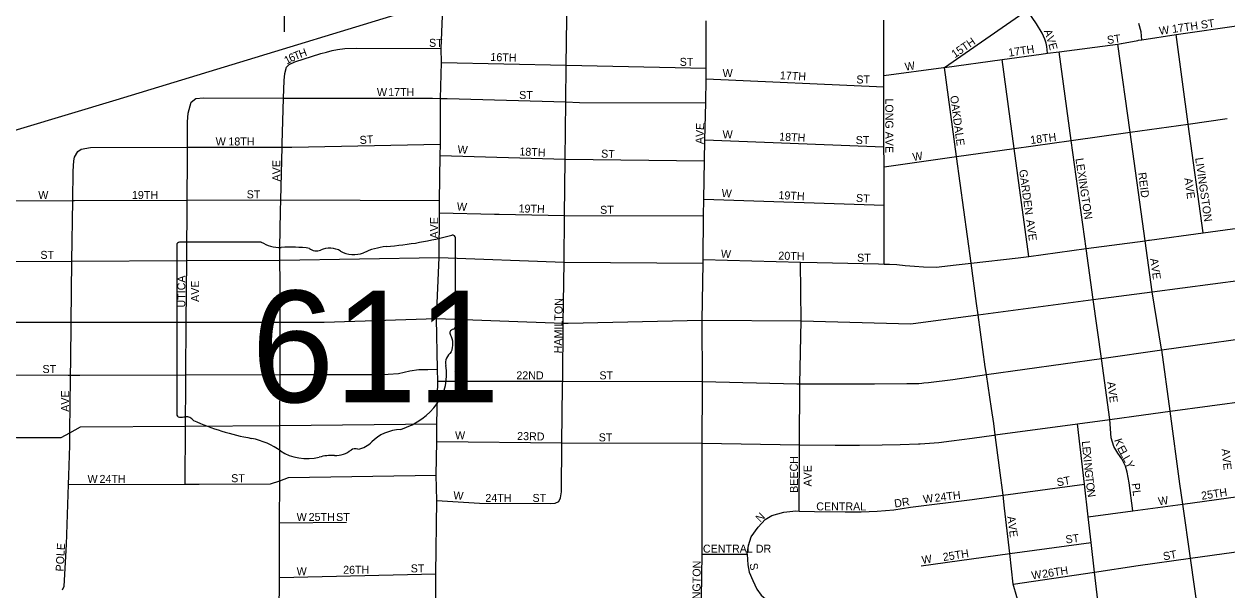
# Model space of a CAD drawing. Extents: x 1857828 to 2277390, y 930619 to 1324581.
# Drawn here: x 2052272 to 2059789, y 1255617 to 1259151 of the extents above; entities that cross this region are included whole.
import ezdxf

# ---------------------------------------------------------------- set-up
doc = ezdxf.new("R2010")
doc.units = 0
for name, color, linetype in [('GM_X_City_Street', 7, 'Continuous'), ('GM_X_City_Street_Text', 7, 'Continuous'), ('GM_X_Rail_Line', 7, 'Continuous'), ('GM_X_State_Location', 7, 'Continuous'), ('GM_X_State_Route', 7, 'Continuous'), ('GM_X_State_Shield', 7, 'Continuous')]:
    doc.layers.add(name, color=color, linetype=linetype)

msp = doc.modelspace()

# ---------------------------------------------------------------- linework, layer by layer
at = {"layer": 'GM_X_City_Street'}
for points in [[(2058668.6, 1258968.7), (2058662.8, 1259010.8), (2058660.5, 1259032.8), (2058650.2, 1259056.9), (2058633.7, 1259094.9), (2058599, 1259152.7), (2058541.7, 1259237.8), (2058321.9, 1259564.8), (2058098.2, 1259897.5), (2057867.7, 1260240.3), (2057780.8, 1260369.7)], [(2058024.2, 1258880.5), (2058541.7, 1259237.8), (2058989.7, 1259547.1), (2059478.5, 1259884.5)], [(2053900.3, 1259102.5), (2053899.4, 1259335.2), (2053899.3, 1259343.5), (2053894.9, 1259684.1)], [(2055637.8, 1256903.3), (2055638, 1256921.8), (2055642.1, 1257283.9), (2055646.5, 1257664.5), (2055649.9, 1257954.5), (2055654, 1258306.7), (2055658.1, 1258664.8), (2055660.8, 1258894), (2055664.1, 1259184.9), (2055666.2, 1259368.8)], [(2054848.2, 1255160.7), (2054844.8, 1255718.4), (2054852.3, 1256174.6), (2054846.6, 1256333.5), (2054852.3, 1256544.1), (2054852.3, 1256653.4), (2054858, 1256920.3), (2054856.1, 1256996), (2054848.5, 1257312.1), (2054865.6, 1257692.5), (2054869.2, 1257972.5), (2054867.5, 1258048.4), (2054873.2, 1258331), (2054875.1, 1258400.4), (2054874.1, 1258687.3), (2054880.7, 1258911.5), (2054878.8, 1258998.5), (2054886.5, 1259203.5)], [(2056510.7, 1257302.8), (2056516.3, 1257657.9), (2056516.5, 1257680.5), (2056518.8, 1257952.5), (2056519.8, 1258056.8), (2056523.3, 1258296), (2056525.6, 1258429), (2056531.6, 1258659.9), (2056535, 1258809), (2056535, 1258876.1), (2056534.8, 1259172.1)], [(2057646.2, 1258282.5), (2057646.2, 1258283.1), (2057646, 1258384.2), (2057645, 1258760.1), (2057644.9, 1258830.3), (2057644.1, 1259165), (2057644.1, 1259175.2)], [(2059231.7, 1259049), (2059235.7, 1259049.7), (2059256.9, 1259053.7), (2059252.9, 1259102), (2059238.9, 1259154.2)], [(2059256.9, 1259053.7), (2059471.1, 1259085.6), (2059878.9, 1259143.9)], [(2059640.6, 1257847.3), (2059547.6, 1258526.9), (2059471.1, 1259085.6)], [(2053911.4, 1258881.5), (2053928.7, 1258897.8), (2053964.6, 1258916.2), (2054126.5, 1258968), (2054162.5, 1258976.4), (2054196.5, 1258986.8), (2054230.5, 1258993.2), (2054276.6, 1258997.6), (2054350.7, 1259000.3), (2054878.8, 1258998.5)], [(2058024.4, 1258880.5), (2058384.6, 1258930), (2058628.4, 1258963.5), (2058668.6, 1258968.7), (2058740.1, 1258978), (2059108.3, 1259025.9)], [(2059321.9, 1257478.7), (2059277.8, 1257798.1), (2059184.2, 1258475.9), (2059108.3, 1259025.9), (2059128, 1259029.6)], [(2059128, 1259029.6), (2059129.5, 1259029.9), (2059231.7, 1259049)], [(2058551.7, 1257699.9), (2058460.1, 1258374.1), (2058384.6, 1258930)], [(2059057.6, 1256681.8), (2059005, 1257062.6), (2058954.1, 1257430.2), (2058910.1, 1257748.4), (2058816.7, 1258424.2), (2058740.1, 1258978)], [(2053871.8, 1257024.1), (2053872.5, 1257289.9), (2053872.6, 1257303), (2053871.6, 1257538), (2053870.9, 1257676.8), (2053870.5, 1257752.9), (2053875.5, 1257981.9), (2053877.1, 1258052.7), (2053884.8, 1258383), (2053885.3, 1258403.6), (2053893.7, 1258688.9), (2053897, 1258799.2), (2053901.2, 1258843.4), (2053911.4, 1258881.5)], [(2054880.7, 1258911.5), (2055660.8, 1258894), (2056535, 1258876.1)], [(2057644.9, 1258830.3), (2058018.8, 1258879.8), (2058024.2, 1258880.5), (2058024.4, 1258880.5)], [(2058539, 1255019.9), (2058496.6, 1255319.4), (2058499.1, 1255494.6), (2058454.1, 1255652.4), (2058432.3, 1255843.4), (2058399.7, 1256128.6), (2058389.9, 1256207.9), (2058368.7, 1256379.9), (2058341.3, 1256585.1), (2058331.7, 1256657.3), (2058318.1, 1256749.8), (2058286.5, 1256961.5), (2058279.1, 1257011.1), (2058234.2, 1257335.2), (2058224.6, 1257405.1), (2058190.3, 1257657.4), (2058099.8, 1258323.5), (2058024.2, 1258880.5)], [(2056535, 1258809), (2057645, 1258760.1)], [(2053282.9, 1256906.5), (2053283, 1256914.3), (2053283.3, 1256960.3), (2053285.7, 1257289.7), (2053288.5, 1257673.9), (2053291.2, 1258051.1), (2053293.1, 1258310.5), (2053293.4, 1258381.7), (2053294.1, 1258541.5), (2053298.3, 1258595.7), (2053316.6, 1258663.9)], [(2053316.6, 1258663.9), (2053344.8, 1258685.8), (2053393, 1258689.6), (2053893.7, 1258688.9), (2054825.4, 1258687.5), (2054874.1, 1258687.3), (2054903.3, 1258687.1), (2054913.7, 1258687), (2054916.7, 1258687)], [(2054916.7, 1258687), (2055658.1, 1258664.8), (2055742.1, 1258662.3), (2056531.6, 1258659.9)], [(2057646.2, 1258259.7), (2058099.8, 1258323.5), (2058460.1, 1258374.1), (2058816.7, 1258424.2), (2059184.2, 1258475.9), (2059547.6, 1258526.9), (2059789.9, 1258561)], [(2052607.1, 1258354.6), (2052629.3, 1258370.5), (2052687.5, 1258380.2), (2053293.4, 1258381.7), (2053884.8, 1258383), (2053945.4, 1258383.2), (2054875.1, 1258400.4)], [(2056525.6, 1258429), (2057646, 1258384.2)], [(2052563.1, 1256961.3), (2052563.4, 1257045.2), (2052566.5, 1257289.3), (2052571.4, 1257670.4), (2052576.2, 1258049.1), (2052578.5, 1258232.2), (2052582.8, 1258296.5), (2052586.9, 1258320.5), (2052607.1, 1258354.6)], [(2054873.2, 1258331), (2055654, 1258306.7), (2056523.3, 1258296)], [(2057647.7, 1257652.3), (2057646.8, 1258020.7), (2057646.2, 1258259.7), (2057646.2, 1258282.5)], [(2051367.9, 1258042.2), (2051457.5, 1258046), (2052576.2, 1258049.1), (2052577.8, 1258049.1), (2052587.4, 1258049.2)], [(2052587.4, 1258049.2), (2053291.2, 1258051.1), (2053877.1, 1258052.7), (2054867.5, 1258048.4)], [(2056519.8, 1258056.8), (2057646.8, 1258020.7)], [(2054869.2, 1257972.5), (2055211.5, 1257964.6), (2055241.6, 1257963.9)], [(2055241.6, 1257963.9), (2055649.9, 1257954.5), (2056518.8, 1257952.5)], [(2059305.2, 1257801.8), (2059640.6, 1257847.3), (2060038.3, 1257901.1)], [(2056516.5, 1257680.5), (2057123.7, 1257663.5), (2057228.5, 1257661.7), (2057611.7, 1257653.6), (2057647.7, 1257652.3), (2057679.9, 1257651.2), (2057726, 1257648.9), (2057778.2, 1257642.6), (2057836.3, 1257638.2), (2057892.5, 1257633.9), (2057972.8, 1257633.4), (2058097.2, 1257646.8), (2058190.3, 1257657.4), (2058484.6, 1257690.8), (2058551.7, 1257699.9), (2058910.1, 1257748.4), (2059277.8, 1257798.1), (2059298.4, 1257800.9), (2059305.2, 1257801.8)], [(2051371.8, 1257664.5), (2052571.4, 1257670.4), (2053288.5, 1257673.9), (2053870.9, 1257676.8), (2054865.6, 1257692.5), (2055646.5, 1257664.5), (2056516.3, 1257657.9)], [(2057116.5, 1256109.2), (2057118.4, 1256522.4), (2057120.2, 1256903.3), (2057129, 1257297), (2057123.7, 1257663.5)], [(2059757.7, 1253849.1), (2059767.8, 1253889.4), (2059778.7, 1253933.4), (2059751.9, 1254138.8), (2059712.6, 1254439.9), (2059709.1, 1254494.4), (2059708.9, 1254498.2), (2059709.1, 1254550.5), (2059707.4, 1254632.8), (2059705.8, 1254705.1), (2059692.1, 1254799.6), (2059687.4, 1254837.8), (2059649.5, 1255145), (2059608.7, 1255475.2), (2059561, 1255814.5), (2059513.4, 1256153.2), (2059495.7, 1256279.1), (2059434, 1256732.5), (2059381.7, 1257115.6), (2059381, 1257121.4), (2059321.9, 1257478.7)], [(2056512.2, 1256884.5), (2056512.5, 1256918), (2056510.7, 1257302.8)], [(2057895.9, 1256910), (2057923.5, 1256912.6), (2058076.1, 1256931.9), (2058286.5, 1256961.5), (2059005, 1257062.6), (2059381.7, 1257115.6), (2060126.8, 1257220.5)], [(2052553.7, 1256958.8), (2052563.1, 1256958.8), (2052621.2, 1256958.5), (2053283.3, 1256960.3), (2053871.6, 1256961.8), (2054322.5, 1256963), (2054495.1, 1256962), (2054547.2, 1256963.8), (2054611.5, 1256969.4), (2054683.8, 1256985.1), (2054740, 1256992.8), (2054796.2, 1256994.5), (2054856.1, 1256996)], [(2053870, 1256399.6), (2053870.7, 1256644), (2053871.5, 1256952.6), (2053871.6, 1256961.8), (2053871.8, 1257024.1)], [(2051374.4, 1256963.8), (2052546.6, 1256958.9), (2052553.7, 1256958.8)], [(2052557.5, 1256598.5), (2052557.5, 1256599), (2052557.5, 1256599.9), (2052557.5, 1256605.4), (2052563, 1256938.8), (2052563.1, 1256958.8), (2052563.1, 1256961.3)], [(2053278.4, 1256277.3), (2053281, 1256639.8), (2053282.9, 1256906.5)], [(2054858, 1256920.3), (2055638, 1256921.8), (2056512.5, 1256918), (2057100.9, 1256903.2), (2057120.2, 1256903.3), (2057586.4, 1256904.5), (2057789.1, 1256905.4), (2057863.3, 1256907), (2057883.4, 1256908.8), (2057895.9, 1256910)], [(2055613.2, 1256168.4), (2055624.4, 1256191.3), (2055630, 1256229.5), (2055633.6, 1256536.6), (2055637.6, 1256890.4), (2055637.8, 1256903.3)], [(2056500, 1255159), (2056510.7, 1255840.2), (2056509, 1256533.2), (2056512.2, 1256884.5)], [(2058335.6, 1256584.3), (2058341.3, 1256585.1), (2058854.5, 1256654.3), (2059057.6, 1256681.8), (2059268.8, 1256710.2), (2059434, 1256732.5), (2060177.7, 1256832.6)], [(2059201.6, 1256110.7), (2059179.1, 1256285.2), (2059165, 1256351.5), (2059155, 1256389.6), (2059132.9, 1256435.8), (2059106.8, 1256472), (2059082.7, 1256512.1), (2059066.6, 1256566.4), (2059057.6, 1256681.8)], [(2051353.5, 1256571.4), (2052224.3, 1256569.1), (2052503.2, 1256569.5), (2052557.5, 1256599), (2052623.8, 1256635.1), (2053281, 1256639.8), (2053870.7, 1256644), (2054852.3, 1256653.4)], [(2052511.2, 1255617.4), (2052523.3, 1255641.4), (2052536.5, 1255900.4), (2052550.3, 1256276.1), (2052552.4, 1256332.2), (2052557.1, 1256519), (2052557.5, 1256598.5)], [(2059205.7, 1253826.9), (2059172.5, 1254060.4), (2059122.4, 1254412.4), (2059113.9, 1254472.4), (2059094.2, 1254612.8), (2059077.2, 1254746.1), (2059072.2, 1254785.3), (2059040.1, 1255060.6), (2059001.8, 1255390.2), (2058962.4, 1255728.3), (2058940.9, 1255912.9), (2058922.3, 1256072.7), (2058898.4, 1256277.4), (2058854.5, 1256654.3)], [(2054852.3, 1256544.1), (2055633.6, 1256536.6), (2056509, 1256533.2), (2057118.4, 1256522.4), (2057340, 1256520.2), (2057492.5, 1256521.4), (2057635, 1256522.6), (2057747.4, 1256526), (2057861.4, 1256529), (2057870.6, 1256529.2)], [(2057870.6, 1256529.2), (2057871.7, 1256529.3), (2057929.9, 1256533), (2057988.1, 1256538.7), (2058068.4, 1256548.2), (2058196.9, 1256565.6), (2058331.7, 1256583.8), (2058335.6, 1256584.3)], [(2053860, 1255114.9), (2053865.1, 1255378.9), (2053866.8, 1255463.1), (2053867.7, 1255693.9), (2053868.4, 1255838.7), (2053868.9, 1256035.4), (2053869.7, 1256299.2), (2053869.7, 1256325), (2053870, 1256399.6)], [(2052550.3, 1256276.1), (2053278.4, 1256277.3), (2053366.7, 1256277.4), (2053812, 1256278.9), (2053869.7, 1256299.2), (2053924.6, 1256318.5), (2054846.6, 1256333.5)], [(2057812.2, 1256133.6), (2058197, 1256181.5), (2058389.9, 1256207.9), (2058898.4, 1256277.4)], [(2058922.3, 1256072.7), (2059201.6, 1256110.7), (2059513.4, 1256153.2), (2059860.3, 1256200.4), (2060253.8, 1256254)], [(2054852.3, 1256174.6), (2055117.6, 1256159.1), (2055561, 1256156.6), (2055591.1, 1256158.4), (2055613.2, 1256168.4)], [(2056790.2, 1255841.2), (2056800.2, 1255895.4), (2056816.2, 1255947.6), (2056860.2, 1256009.8), (2056904.3, 1256055.9), (2056944.3, 1256082), (2057020.5, 1256102), (2057094.6, 1256110), (2057116.5, 1256109.2), (2057210.9, 1256105.9), (2057403.3, 1256103.7), (2057503.6, 1256105.7), (2057603.8, 1256109.6), (2057708, 1256117.6), (2057812.2, 1256133.6)], [(2053868.9, 1256035.4), (2054286.4, 1256039.5)], [(2057877.6, 1255767.6), (2058432.3, 1255843.4), (2058940.9, 1255912.9)], [(2058454.1, 1255652.4), (2058962.4, 1255728.3), (2059235.4, 1255769), (2059561, 1255814.5), (2060298, 1255917.3)], [(2056510.7, 1255840.2), (2056790.2, 1255841.2)], [(2056790.2, 1255841.2), (2056794.2, 1255772.9), (2056804.3, 1255728.7), (2056826.4, 1255676.5), (2056850.5, 1255622.3), (2056878.6, 1255584.1), (2056920.7, 1255547.9), (2056970.8, 1255523.8), (2057047, 1255509.7), (2057105.8, 1255503.8), (2057127.2, 1255501.6), (2057263.5, 1255501.5), (2057377.7, 1255503.5), (2057477.9, 1255505.4), (2057542.1, 1255507.4), (2057584.2, 1255501.3), (2057644.3, 1255491.2), (2057701.2, 1255489.6), (2057820.2, 1255421), (2057867.5, 1255377.4)], [(2053867.7, 1255693.9), (2054844.8, 1255718.4)]]:
    msp.add_lwpolyline(points, dxfattribs=at)
at = {"layer": 'GM_X_Rail_Line'}
msp.add_lwpolyline([(2044683.2, 1256198.2), (2047003.1, 1256900.8), (2049235, 1257574.5), (2049628.9, 1257694.6), (2049728.7, 1257726.8), (2049921.1, 1257796), (2050159.4, 1257869.2), (2051356.3, 1258230.8), (2052847.1, 1258678.3), (2055337.6, 1259437.3), (2056506.8, 1259789.8), (2056581.8, 1259814.4), (2056641.8, 1259834.5), (2056714.6, 1259862.5), (2056780.4, 1259889.1), (2056853.9, 1259922.2), (2056942.1, 1259963.8), (2057085.6, 1260039.1), (2057160.2, 1260084.6), (2057233.4, 1260130.8), (2057527, 1260327), (2057787.1, 1260503.3), (2058204.4, 1260784)], dxfattribs=at)
at = {"layer": 'GM_X_State_Route'}
for points in [[(2054848.5, 1257312.1), (2054848.5, 1257312.1), (2055642.1, 1257283.9), (2055672.5, 1257283.8), (2056510.7, 1257302.8), (2057129, 1257297), (2057814.2, 1257279.8), (2058234.2, 1257335.2), (2058954.1, 1257430.2), (2059321.9, 1257478.7), (2060079.7, 1257578.7)], [(2050157.6, 1257272.9), (2050397.9, 1257275.1), (2051068.4, 1257281.4), (2051376, 1257284.4), (2051874.2, 1257289.1), (2052566.5, 1257289.3), (2053285.7, 1257289.7), (2053872.5, 1257289.9), (2053894.2, 1257289.9), (2053900.1, 1257289.9)], [(2053900.1, 1257289.9), (2054146.7, 1257290.1), (2054848.5, 1257312.1)]]:
    msp.add_lwpolyline(points, dxfattribs=at)
at = {"layer": 'GM_X_State_Shield'}
for p, q in [((2054967.4, 1257263.1), (2054967.4, 1257815.8)), ((2053227.2, 1257771.5), (2053227.2, 1256714.8)), ((2053754, 1257789.7), (2053244.3, 1257789.7)), ((2054967.2, 1257263.2), (2054967.4, 1257263.1))]:
    msp.add_line(p, q, dxfattribs=at)
for centre, major_axis, start_param, end_param in [((2054347.5, 1259230.2), (1845.5, 0), 4.814394, 5.042369), ((2054948.1, 1257818.1), (19.4, 0), 6.141152, 7.989035), ((2053247.1, 1257773.7), (20.2, 0), 1.712693, 3.28349), ((2053875.3, 1257912.3), (195.5, 0), 4.042523, 4.731795), ((2053940.2, 1257196.5), (702, 0), 1.404758, 1.657858), ((2054099.5, 1257779.2), (56.4, 0), 3.836095, 5.185415), ((2054182.3, 1257657.1), (117.3, 0), 0.950623, 2.079405), ((2054333.7, 1257824.6), (141.1, 0), 4.081561, 5.145723), ((2054582.9, 1257466.9), (371.3, 0), 1.699011, 2.107814), ((2054962.9, 1257222.5), (30, 0), 1.883978, 3.671073), ((2054772.2, 1257152.7), (180, 0), 5.934695, 6.695948), ((2054946.7, 1257261), (20.7, 0), 5.05454, 6.418171), ((2055036.8, 1257031.8), (130.9, 0), 2.387724, 3.262537), ((2054450.9, 1256961.5), (461.6, 0), 5.101752, 6.440018), ((2053247.3, 1256712.5), (20.3, 0), 3.00124, 4.508301), ((2053250.4, 1256820.6), (155.2, 0), 4.665946, 4.897461), ((2053282.2, 1256653.9), (56, 0), 0.519207, 1.627899), ((2053988.8, 1257603.2), (1332.7, 0), 4.195997, 4.488961), ((2054645.5, 1256418.2), (252.8, 0), 1.647645, 2.488434), ((2053591.4, 1256240.1), (417, 0), 0.823519, 1.323587), ((2054325.2, 1256612.4), (149.1, 0), 4.937069, 5.64225), ((2054042.4, 1256648.6), (264.6, 0), 4.026481, 4.996735), ((2054195.3, 1256283.3), (217.4, 0), 1.495662, 1.94098), ((2054214.6, 1256569.5), (141, 0), 4.691044, 5.507374), ((2054342.2, 1256467.2), (39.7, 0), 1.147584, 2.315152)]:
    msp.add_ellipse(centre, major_axis=major_axis, ratio=0.8, start_param=start_param, end_param=end_param, dxfattribs=at)

# ---------------------------------------------------------------- texts
at = {"layer": 'GM_X_City_Street_Text'}
for s, rotation, p in [('W 17TH ST', 8.24245, (2059368.9, 1259083.6)), ('A', 290.43323, (2058643.9, 1259108.4)), ('V', 288.46261, (2058659.1, 1259067.6)), ('ST', 7.59083, (2059043.1, 1259026.4)), ('ST', 0.00001, (2054802.7, 1259008.9)), ('15TH', 34.70215, (2058088.6, 1258936.8)), ('17TH', 8.88878, (2058426.9, 1258947.1)), ('E', 284.67262, (2058672.8, 1259026.7)), ('1', 28.3663, (2053913.8, 1258897.7)), ('6', 25.92256, (2053940.4, 1258912.1)), ('T', 21.53763, (2053967.2, 1258925.1)), ('H', 20.26696, (2053999.6, 1258938)), ('16TH', 358.21116, (2055185.8, 1258920.9)), ('ST', 0.00001, (2056369.1, 1258890.1)), ('W', 0.00001, (2056637.5, 1258819.7)), ('17TH', 357.27517, (2056994.4, 1258806.4)), ('W', 8.74111, (2057780.1, 1258859.2)), ('ST', 0.00001, (2057473.5, 1258780.1)), ('W', 0.00001, (2054477.1, 1258700.9)), ('17TH', 0.00001, (2054547.5, 1258700.9)), ('ST', 0.00001, (2055365.9, 1258683.3)), ('OAKDALE', 277.64956, (2058059.3, 1258701.5)), ('LONG AVE', 270, (2057654.5, 1258687)), ('V', 87.79235, (2056519, 1258444.5)), ('E', 87.59586, (2056520.6, 1258488.5)), ('W', 0.00001, (2056637.5, 1258436.9)), ('W', 0.00001, (2053469.5, 1258392.9)), ('18TH', 0.00001, (2053548.7, 1258392.9)), ('ST', 3.57378, (2054370.9, 1258401.7)), ('A', 88.90669, (2056518.1, 1258400.8)), ('18TH', 357.27517, (2056990, 1258423.7)), ('ST', 0.00001, (2057469.1, 1258401.7)), ('18TH', 7.3488, (2058563.5, 1258401.6)), ('W', 355.60387, (2054979.4, 1258344.5)), ('18TH', 357.27517, (2055366.4, 1258331.2)), ('ST', 356.42537, (2055876.9, 1258318.1)), ('W', 8.74363, (2057828.5, 1258296)), ('AVE', 90, (2053873.7, 1258167.9)), ('LEXINGTON', 278.63844, (2058842.4, 1258310.1)), ('LIVINGSTON', 278.22742, (2059590.4, 1258314.4)), ('GARDEN', 277.85294, (2058490.4, 1258239.5)), ('REID', 277.35574, (2059234, 1258221.9)), ('AVE', 278.13339, (2059522.9, 1258187.8)), ('W', 0.00001, (2052360.7, 1258058.5)), ('19TH', 0.00001, (2052945.9, 1258058.5)), ('ST', 0.00001, (2053663.1, 1258062.9)), ('W', 355.60387, (2056629.4, 1258071.6)), ('19TH', 357.27517, (2056985.6, 1258058.5)), ('W', 355.60387, (2054975, 1257988)), ('19TH', 358.63682, (2055361.8, 1257974.9)), ('ST', 356.42537, (2057469.7, 1258040.9)), ('ST', 0.00001, (2055871.9, 1257966.1)), ('AVE', 90, (2054859.3, 1257811.5)), ('AVE', 277.85664, (2058534.4, 1257927.1)), ('ST', 0.00001, (2052373.9, 1257684.5)), ('W', 355.60387, (2056625, 1257693.2)), ('20TH', 358.63682, (2056985.4, 1257680.1)), ('ST', 0.00001, (2057477.9, 1257666.9)), ('AVE', 278.12574, (2059308.9, 1257685.2)), ('UTICA', 90, (2053279.7, 1257380.3)), ('AVE', 90, (2053365.8, 1257415.5)), ('HAMILTON', 89.22505, (2055633.7, 1257094.1)), ('ST', 0.00001, (2052387.1, 1256971.7)), ('W', 0.00001, (2054961.1, 1256932.1)), ('22ND', 0.00001, (2055348.3, 1256932.1)), ('ST', 0.00001, (2055867.5, 1256932.1)), ('AVE', 277.84924, (2059040.4, 1256915.1)), ('AVE', 90, (2052553.7, 1256729.1)), ('W', 0.00001, (2054965.5, 1256558.1)), ('23RD', 358.66861, (2055352.9, 1256553.7)), ('ST', 0.00001, (2055863.1, 1256544.9)), ('L', 275.63452, (2058882.1, 1256545.2)), ('K', 287.35664, (2059084, 1256553.9)), ('E', 298.50239, (2059101.2, 1256502.3)), ('BEECH', 90, (2057107.7, 1256223.1)), ('E', 275.63452, (2058885.6, 1256510.1)), ('X', 275.62793, (2058889, 1256475.1)), ('L', 298.68297, (2059118, 1256471.2)), ('L', 298.66716, (2059134.9, 1256440.3)), ('AVE', 275.90306, (2059755.7, 1256496.8)), ('AVE', 90, (2057193.7, 1256262.7)), ('I', 275.60618, (2058893.3, 1256431.3)), ('N', 275.65184, (2058895.5, 1256409.4)), ('Y', 292.67033, (2059151.2, 1256410.7)), ('W', 0.00001, (2052668.7, 1256285.3)), ('24TH', 0.00001, (2052743.5, 1256285.3)), ('ST', 0.00001, (2053566.3, 1256289.7)), ('ST', 10.61471, (2058730.2, 1256263.1)), ('G', 275.62793, (2058899.8, 1256365.6)), ('T', 275.92091, (2058904.1, 1256321.5)), ('W', 355.60387, (2054953, 1256184)), ('24TH', 7.12081, (2057965.2, 1256166.4)), ('O', 278.03384, (2058908, 1256284.5)), ('N', 278.95715, (2058914.3, 1256240.1)), ('PL', 277.12166, (2059193.8, 1256281.3)), ('25TH', 8.88983, (2059632.5, 1256179.6)), ('24TH', 0.00001, (2055154.7, 1256166.5)), ('ST', 0.00001, (2055449.5, 1256166.5)), ('CENTRAL', 0.00001, (2057222.7, 1256113.7)), ('DR', 8.98976, (2057714.1, 1256131.1)), ('W', 8.74111, (2057894.5, 1256157.6)), ('W', 9.45641, (2059364, 1256144.3)), ('W', 0.00001, (2053975.5, 1256047.7)), ('25TH', 0.00001, (2054050.3, 1256047.7)), ('ST', 0.00001, (2054221.9, 1256047.7)), ('N', 45, (2056872.9, 1256036.1)), ('AVE', 277.85664, (2058415.6, 1256074.8)), ('ST', 7.12165, (2058783.6, 1255906.8)), ('POLE', 86.73164, (2052518.5, 1255730.8)), ('CENTRAL DR', 0.00001, (2056514.3, 1255849.7)), ('25TH', 8.87649, (2058017.7, 1255796.8)), ('ST', 10.61471, (2059394.6, 1255801.1)), ('26TH', 0.00001, (2054265.9, 1255717.7)), ('ST', 0.00001, (2054688.3, 1255726.5)), ('WASHINGTON', 89.39078, (2056496.1, 1255338.8)), ('S', 279.63798, (2056805.2, 1255780.5)), ('W', 8.74111, (2057885.7, 1255779.2)), ('W', 0.00001, (2053975.5, 1255708.9)), ('W', 9.45641, (2058572, 1255682.3)), ('26TH', 8.88878, (2058638.1, 1255691.2))]:
    msp.add_text(s, height=50, rotation=rotation, dxfattribs=at).set_placement(p)
at = {"layer": 'GM_X_State_Location'}
for s in ['s', 'r']:
    msp.add_text(s, height=1, dxfattribs=at).set_placement((2054077.7, 1257172.9))
msp.add_text('611', height=1, rotation=0.00001, dxfattribs=at).set_placement((2053724.7, 1257100.2))
at = {"layer": 'GM_X_State_Shield'}
msp.add_text('611', height=696.1, dxfattribs=at).set_placement((2053692.5, 1256789.4))

doc.saveas('drawing.dxf')
